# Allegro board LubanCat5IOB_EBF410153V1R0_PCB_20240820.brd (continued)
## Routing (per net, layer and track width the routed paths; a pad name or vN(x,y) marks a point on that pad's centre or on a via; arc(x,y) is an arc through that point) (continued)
HDMI1_EARC-: length 14.2
  TOP w0.114: v1(97.28,77.97) 97.62,78.31 arc(97.67,78.38) 97.68,78.45 97.68,78.64 arc(97.67,78.72) 97.62,78.8 D34.2 97.53,79.1 arc(97.55,79.2) 97.61,79.28 97.63,79.31 arc(97.68,79.38) 97.69,79.46 97.69,80.02 arc(97.83,80.35) 98.16,80.49 98.84,80.49 arc(99.07,80.72) 98.84,80.95 97.27,80.95 arc(96.93,81.09) 96.79,81.43 96.79,81.62 arc(96.73,81.76) 96.59,81.81 96.34,81.81 arc(96.02,81.95) 95.89,82.27 95.89,82.28 arc(96.02,82.62) 96.35,82.75 96.56,82.75 arc(96.72,82.82) 96.79,82.98 96.79,83.1 arc(96.86,83.47) 97.07,83.79 97.42,84.13 arc(97.63,84.45) 97.7,84.82 97.7,84.98 arc(97.63,85.14) 97.47,85.21 97.27,85.21 arc(97.22,85.21) 97.18,85.21 arc(97.09,85.22) 96.99,85.21 arc(96.99,85.21) 96.99,85.21 arc(96.75,85.12) 96.58,84.94 arc(96.57,84.92) 96.56,84.91 arc(96.55,84.88) 96.55,84.84 96.55,84.84 arc(96.54,84.82) 96.53,84.8 arc(96.37,84.43) 96.13,84.11 J17.19
HDMI1_TX_ON: length 50.1
  TOP w0.152: J4.91 v2(86.04,64.36)
  BOTTOM w0.152: R190.1 124.59,75.31 124.18,74.9 120.75,74.9 120.47,75.18 119.08,75.18 118.82,74.93 118.82,74.04 118.57,73.79 117.47,73.79 117.09,73.4 117.09,71.75 116.71,71.37 115.95,71.37 115.57,70.99 115.57,70.36 115.19,69.98 113.83,69.98 112.32,68.47 112.32,64.57 111.06,63.31 88.32,63.31 87.68,63.95 86.45,63.95 v2(86.04,64.36)
HDMI_RX0N_PORT: length 16.8
  TOP w0.114: J18.9 106.89,89.85 108.52,89.85 108.83,90.17 109.45,90.17 109.85,89.77 109.85,89.77 112.38,87.24 112.38,86.87 112.19,86.68 112.19,86.22 112.38,86.03 112.38,85.57 112.19,85.38 112.19,84.93 112.38,84.74 112.38,84.28 112.19,84.09 112.19,83.63 112.38,83.44 112.38,80.83 112.26,80.71 U24.7 U24.4 112.26,79.06 112.39,78.93 112.39,78.34 R206.2
HDMI_RX0P_PORT: length 16.9
  TOP w0.114: J18.7 106.89,91 108.26,91 108.85,90.41 109.55,90.41 109.95,90.01 109.95,90.01 112.62,87.34 112.62,80.84 112.76,80.71 U24.6 U24.5 112.76,79.06 112.63,78.93 112.63,78.37 R205.2
HDMI_RX1N_PORT: length 20.6
  TOP w0.114: R204.2 114.95,76.34 114.95,78.93 114.82,79.06 U23.1 U23.10 114.82,80.72 114.95,80.84 114.95,82.63 114.78,82.8 114.78,83.25 114.95,83.42 114.95,83.66 114.78,83.82 114.78,84.33 114.95,84.5 114.95,84.95 114.78,85.12 114.78,85.63 114.95,85.79 114.95,86.11 109.01,92.04 108.34,92.04 J18.6
HDMI_RX1P_PORT: length 20.5
  TOP w0.114: R203.2 115.19,76.31 115.19,78.93 115.32,79.06 U23.2 U23.9 115.32,80.71 115.19,80.84 115.19,86.21 109.11,92.28 108.34,92.28 J18.4
HDMI_RX2N_PORT: length 21.8
  TOP w0.114: J18.3 106.89,93.31 108.22,93.31 108.61,93.7 108.78,93.7 109.61,92.87 109.61,92.62 109.93,92.29 110.18,92.29 110.51,91.97 110.51,91.72 110.83,91.4 111.08,91.4 111.25,91.22 111.25,91.02 111.58,90.7 111.78,90.7 112.1,90.38 112.1,90.17 112.42,89.85 112.63,89.85 116.45,86.02 116.45,80.84 116.32,80.71 U23.7 U23.4 116.32,79.06 116.45,78.93 116.45,78.34 R202.2
HDMI_RX2P_PORT: length 21.7
  TOP w0.114: R201.2 117.08,77.97 116.69,78.36 116.69,78.93 116.82,79.06 U23.5 U23.6 116.82,80.71 116.69,80.84 116.69,86.12 108.88,93.94 108.67,93.94 108.1,94.51 106.93,94.51 J18.1
HDMI_RX_CEC_M1: length 80.2
  TOP w0.152: v1(127.78,84.71) 128.24,84.25 128.86,84.25 R198.2 128.59,83.37 Q25.2 ; J4.74 82.44,67.32 v2(82.04,66.92)
  ART03 w0.152: v1(127.78,84.71) 127.46,84.39 115.6,84.39 111.18,79.97 108.92,79.97 107.77,78.83 107.19,78.83 106.76,78.4 106.76,77.56 106.25,77.05 96.01,77.05 95.4,76.44 85.85,76.44 85.04,77.26 80.34,77.26 79.96,77.64 79.96,82.62 v1(80.47,83.13)
  BOTTOM w0.152: v1(80.47,83.13) 80.47,81.09 81.41,80.15 81.41,68.34 81.67,68.08 81.67,67.29 v2(82.04,66.92)
HDMI_RX_CEC_PORT: length 34.2
  TOP w0.152: R209.2 129.54,78.6 v1(129.54,79.18) Q25.3
  BOTTOM w0.152: J18.13 105.54,86.19 105.54,82.39 107.8,80.13 113.68,80.13 D44.2 115.39,78.42 126.56,78.42 127.31,79.18 v1(129.54,79.18)
HDMI_RX_CLKN: length 80.7
  TOP w0.114: R208.1 110.88,74.55 110.88,73.95 110.43,73.5 110.43,70.24 110.2,70.02 108.81,70.02 108.44,69.65 108.44,61.65 103.33,56.54 98.41,56.54 94.04,52.17 90.21,52.17 90.04,52.34 89.59,52.34 89.42,52.17 88.96,52.17 88.8,52.34 88.34,52.34 88.18,52.17 87.72,52.17 87.56,52.34 87.1,52.34 86.93,52.17 86.48,52.17 86.31,52.34 85.85,52.34 85.69,52.17 85.23,52.17 85.07,52.34 84.61,52.34 84.44,52.17 83.99,52.17 83.82,52.34 83.36,52.34 83.2,52.17 82.08,52.17 v1(81.81,52.44) ; J4.65 80.84,63.92 v2(80.44,63.52)
  BOTTOM w0.114: v2(80.44,63.52) 80.29,63.37 80.29,62.03 80.42,61.89 81.87,61.89 82.14,61.62 82.14,61.23 81.87,60.95 80.42,60.95 80.29,60.82 80.29,60.63 80.42,60.5 81.87,60.5 82.14,60.22 82.14,59.83 81.87,59.56 80.42,59.56 80.29,59.42 80.29,59.23 80.42,59.1 81.87,59.1 82.14,58.82 82.14,58.43 81.87,58.16 80.42,58.16 80.29,58.03 80.29,57.84 80.42,57.7 81.87,57.7 82.14,57.43 82.14,57.04 81.87,56.76 80.42,56.76 80.29,56.63 80.29,56.44 80.42,56.3 81.87,56.3 82.14,56.03 82.14,55.64 81.87,55.37 80.42,55.37 80.29,55.23 80.29,55.04 80.42,54.91 81.87,54.91 82.14,54.63 82.14,54.24 81.87,53.97 80.42,53.97 80.29,53.83 80.29,52.47 80.61,52.15 81.53,52.15 v1(81.81,52.44)
HDMI_RX_CLKP: length 80.7
  TOP w0.114: R207.1 111.12,74.55 111.12,73.85 110.67,73.4 110.67,70.14 110.3,69.78 108.91,69.78 108.68,69.55 108.68,61.55 103.43,56.3 98.51,56.3 94.14,51.93 82.13,51.93 v1(81.81,51.62) ; J4.63 v2(80.44,64.36)
  BOTTOM w0.114: v1(81.81,51.62) 81.53,51.91 80.51,51.91 80.05,52.37 80.05,53.93 80.32,54.21 81.77,54.21 81.9,54.34 81.9,54.53 81.77,54.67 80.32,54.67 80.05,54.94 80.05,55.33 80.32,55.61 81.77,55.61 81.9,55.74 81.9,55.93 81.77,56.06 80.32,56.06 80.05,56.34 80.05,56.73 80.32,57 81.77,57 81.9,57.14 81.9,57.33 81.77,57.46 80.32,57.46 80.05,57.74 80.05,58.13 80.32,58.4 81.77,58.4 81.9,58.53 81.9,58.72 81.77,58.86 80.32,58.86 80.05,59.13 80.05,59.52 80.32,59.8 81.77,59.8 81.9,59.93 81.9,60.12 81.77,60.25 80.32,60.25 80.05,60.53 80.05,60.92 80.32,61.19 81.77,61.19 81.9,61.33 81.9,61.52 81.77,61.65 80.32,61.65 80.05,61.93 80.05,63.96 v2(80.44,64.36)
HDMI_RX_D0N: length 78.8
  TOP w0.114: J4.61 80.04,63.92 v2(79.64,63.52) ; R206.1 112.01,76.52 112.4,76.13 112.4,74.95 113.25,74.11 113.25,68.49 113.04,68.29 109.59,68.29 109.27,67.97 109.27,67.48 109.55,67.2 110.75,67.2 110.88,67.07 110.88,66.88 110.75,66.75 109.55,66.75 109.27,66.47 109.27,64.15 109.55,63.87 111.56,63.87 111.7,63.74 111.7,63.55 111.56,63.41 109.55,63.41 109.27,63.14 109.27,62.75 109.55,62.47 110.47,62.47 110.6,62.34 110.6,62.15 110.47,62.02 109.55,62.02 109.27,61.74 109.27,60.9 103.77,55.4 98.53,55.4 93.94,50.81 88.89,50.81 88.72,50.99 88.26,50.99 88.08,50.81 87.62,50.81 87.45,50.99 86.99,50.99 86.81,50.81 86.35,50.81 86.18,50.99 85.72,50.99 85.54,50.81 85.08,50.81 84.91,50.99 84.45,50.99 84.27,50.81 83.81,50.81 83.64,50.99 83.18,50.99 83,50.81 81.06,50.81 v1(80.77,51.1)
  BOTTOM w0.114: v1(80.77,51.1) 80.48,50.81 79.74,50.81 79.49,51.07 79.49,63.37 v2(79.64,63.52)
HDMI_RX_D0P: length 78.8
  TOP w0.114: J4.59 v2(79.64,64.36) ; R205.1 113.03,76.52 112.64,76.13 112.64,75.05 113.49,74.21 113.49,68.39 113.14,68.05 109.69,68.05 109.51,67.87 109.51,67.58 109.65,67.45 110.85,67.45 111.12,67.17 111.12,66.78 110.85,66.51 109.65,66.51 109.51,66.37 109.51,64.25 109.65,64.11 111.66,64.11 111.94,63.84 111.94,63.45 111.66,63.17 109.65,63.17 109.51,63.04 109.51,62.85 109.65,62.72 110.57,62.72 110.85,62.44 110.85,62.05 110.57,61.78 109.65,61.78 109.51,61.64 109.51,60.8 103.87,55.16 98.63,55.16 94.04,50.57 81.06,50.57 v1(80.77,50.29)
  BOTTOM w0.114: v1(80.77,50.29) 80.48,50.57 79.64,50.57 79.25,50.97 79.25,63.96 v2(79.64,64.36)
HDMI_RX_D1N: length 74.4
  TOP w0.114: R204.1 114.55,74.49 114.94,74.1 114.94,67.47 114.78,67.31 112.98,67.31 112.67,67.01 112.67,66.56 112.95,66.29 114.79,66.29 114.92,66.16 114.92,65.97 114.79,65.83 112.95,65.83 112.67,65.56 112.67,62.75 104.32,54.4 98.74,54.4 93.91,49.56 88.31,49.56 88.12,49.75 87.66,49.75 87.47,49.56 87.02,49.56 86.82,49.75 86.37,49.75 86.18,49.56 85.72,49.56 85.53,49.75 85.07,49.75 84.88,49.56 84.42,49.56 84.23,49.75 83.78,49.75 83.59,49.56 83.13,49.56 82.94,49.75 82.48,49.75 82.29,49.56 80.16,49.56 v1(79.88,49.83) ; J4.57 79.24,63.92 v2(78.84,63.52)
  BOTTOM w0.114: v1(79.88,49.83) 79.6,49.54 79.07,49.54 78.68,49.94 78.68,63.35 v2(78.84,63.52)
HDMI_RX_D1P: length 74.3
  TOP w0.114: v1(79.88,49.02) 80.18,49.32 94.01,49.32 98.84,54.16 104.42,54.16 112.92,62.65 112.92,65.46 113.05,65.59 114.89,65.59 115.16,65.87 115.16,66.26 114.89,66.53 113.05,66.53 112.92,66.66 112.92,66.91 113.08,67.07 114.88,67.07 115.18,67.37 115.18,74.1 115.57,74.49 R203.1 ; J4.55 v2(78.84,64.36)
  BOTTOM w0.114: v2(78.84,64.36) 78.44,63.95 78.44,49.84 78.97,49.3 79.6,49.3 v1(79.88,49.02)
HDMI_RX_D2N: length 75.3
  TOP w0.114: J4.53 78.44,63.92 v2(78.04,63.52) ; v1(78.87,48.64) 79.15,48.35 81.35,48.35 81.53,48.53 81.98,48.53 82.16,48.35 82.62,48.35 82.8,48.53 83.25,48.53 83.43,48.35 83.89,48.35 84.07,48.53 84.52,48.53 84.7,48.35 85.16,48.35 85.34,48.53 85.79,48.53 85.97,48.35 86.28,48.35 86.43,48.5 86.89,48.5 87.04,48.35 93.95,48.35 98.86,53.25 104.64,53.25 115.89,64.5 115.89,73.65 116.47,74.23 116.47,76.13 116.08,76.52 R202.1
  BOTTOM w0.114: v1(78.87,48.64) 78.58,48.35 78.26,48.35 77.89,48.71 77.89,63.37 v2(78.04,63.52)
HDMI_RX_D2P: length 75.3
  TOP w0.114: R201.1 117.09,76.52 116.71,76.13 116.71,74.13 116.13,73.55 116.13,64.4 104.74,53.01 98.96,53.01 94.05,48.11 79.15,48.11 v1(78.87,47.82) ; J4.51 v2(78.04,64.36)
  BOTTOM w0.114: v1(78.87,47.82) 78.58,48.11 78.16,48.11 77.65,48.61 77.65,63.97 v2(78.04,64.36)
HDMI_RX_DET: length 97.6
  TOP w0.152: v1(80.64,42.46) 81.07,42.03 81.07,31.16 81.61,30.62 81.61,23.66 81.24,23.29 J2.67 ; v1(112.09,43.19) 112.09,50.13 112.6,50.64 116.08,50.64 116.92,51.48 116.92,60.96 117.51,61.55 117.51,68.23 119.51,70.23 119.51,72.96 118.9,73.57 118.9,74.39 117.86,75.44 117.86,77.33 R210.2 118.49,79.96 118.76,80.22 Q29.3
  ART03 w0.152: v1(80.64,42.46) 81.1,42 108.2,42 109.4,43.19 v1(112.09,43.19)
HDMI_RX_HPD_PORT: length 32.3
  BOTTOM w0.152: R214.2 131.74,78.99 131.57,79.17 131.57,80.64 131.32,80.9 124.97,80.9 124.71,80.64 124.71,80.01 124.3,79.59 117.13,79.59 116.46,80.26 116.46,81.53 115.7,82.29 114.94,82.29 D41.2 113.87,81.22 108.43,81.22 106.89,82.77 J18.19
HDMI_RX_HPDOUT_M1: length 80.1
  TOP w0.152: J4.76 v2(82.84,67.76)
  ART03 w0.152: v1(128.78,84.71) 128.15,85.33 117.4,85.33 116.71,86.02 113.28,86.02 112.78,85.51 112.78,82.82 110.64,80.69 106.98,80.69 104.83,78.53 86.23,78.53 85.52,79.24 82.04,79.24 81.64,79.64 81.64,83.96 v1(80.47,85.13)
  BOTTOM w0.152: v2(82.84,67.76) 83.06,67.97 83.06,75.96 82.26,76.76 82.26,80.67 81.38,81.55 81.38,84.83 81.08,85.13 v1(80.47,85.13) ; R212.1 v1(128.78,84.71)
HDMI_RX_SCL_M1: length 76.5
  TOP w0.152: Q24.2 125.29,83.37 R196.2 125.87,83.96 125,84.83 v1(124.18,84.83) ; J4.70 81.64,67.32 v2(81.24,66.92)
  ART03 w0.152: v1(80.47,84.13) 80.98,83.62 80.98,78.37 81.25,78.1 85.11,78.1 85.67,77.54 105.38,77.54 105.69,77.84 105.69,78.17 107.85,80.33 110.97,80.33 115.47,84.83 v1(124.18,84.83)
  BOTTOM w0.152: v2(81.24,66.92) 80.87,67.29 80.87,76.19 81.05,76.37 81.05,80 80.01,81.05 80.01,83.67 v1(80.47,84.13)
HDMI_RX_SDA_M1: length 79.8
  TOP w0.152: v1(122.56,85.87) R199.2 121.98,83.37 Q26.2 ; J4.72 v2(82.04,67.76)
  ART03 w0.152: v1(122.56,85.87) 121.9,86.53 112.5,86.53 112.22,86.25 112.22,82.95 110.46,81.19 106.73,81.19 104.52,78.98 86.61,78.98 85.72,79.87 84.28,79.87 83.97,80.18 83.97,86.04 83.64,86.37 79.88,86.37 79.47,85.96 v1(79.47,85.13)
  BOTTOM w0.152: v1(79.47,85.13) 79.92,84.67 80.7,84.67 81,84.37 81,81.29 81.91,80.39 81.91,76.48 82.55,75.83 82.55,68.27 v2(82.04,67.76)
HDMI_RXCLKN_PORT: length 15.3
  TOP w0.114: R208.2 110.89,76.34 110.89,78.93 110.76,79.06 U24.1 U24.10 110.76,80.71 110.89,80.84 110.89,83.43 109.22,85.1 109.22,85.9 109.02,86.1 109.02,86.56 109.22,86.76 109.22,87.22 109.02,87.42 109.02,87.88 109.22,88.08 109.22,88.32 108.97,88.57 108.34,88.57 J18.12
HDMI_RXCLKP_PORT: length 15.4
  TOP w0.114: J18.10 108.34,88.81 109.07,88.81 109.46,88.42 109.46,85.2 111.13,83.53 111.13,80.84 111.26,80.71 U24.9 U24.2 111.26,79.06 111.13,78.93 111.13,76.31 R207.2
HDMI_RXDDC_SCL_PORT: length 31.9
  TOP w0.152: v1(125.22,80.34) 125.34,80.22 Q24.3 127.85,80.22 128.14,79.93 128.14,77.6 R197.2
  BOTTOM w0.152: J18.15 106.17,85.66 106.17,82.54 108.07,80.64 D43.2 114.85,80.11 115.73,80.11 116.71,79.12 124.84,79.12 125.22,79.5 v1(125.22,80.34)
HDMI_RXDDC_SDA_PORT: length 34.5
  TOP w0.152: v1(124.21,80.34) 124.09,80.22 Q26.3 122.94,79.32 123.16,79.09 127.2,79.09 127.5,78.8 R200.2
  BOTTOM w0.152: v1(124.21,80.34) 123.73,80.81 118.52,80.81 118.06,81.28 118.06,86.21 117.86,86.41 114.51,86.41 114.31,86.21 D42.2 112.9,85.6 112.55,85.95 112.55,87.89 112.17,88.26 109.6,88.26 109.22,87.88 109.22,86.1 108.92,85.8 J18.16
HDMI_TX0_CEC_M0: length 54.5
  TOP w0.152: v1(82.03,70.9) R170.2 82.49,72.1 Q14.2 ; v2(54.72,67.4) 54.33,67.4 54.07,67.66 J3.60
  ART04 w0.152: v1(62.99,82.13) 63.18,82.31 80.59,82.31 80.95,81.95 80.95,79.03 82.03,77.94 v1(82.03,70.9)
  BOTTOM w0.152: v1(62.99,82.13) 62.42,81.55 61.21,81.55 60.93,81.27 60.93,76.47 60.22,75.76 60.22,74.92 59.92,74.61 58.88,74.61 58.57,74.31 58.57,71.87 58.06,71.36 58.06,68.62 57.56,68.11 54.94,68.11 54.72,67.9 v2(54.72,67.4)
HDMI_TX0_CEC_PORT: length 15.1
  TOP w0.152: v1(82.69,78.72) 82.01,78.72 81.53,78.25 Q14.3
  BOTTOM w0.152: J16.13 83.69,85.94 D31.2 82.71,78.74 v1(82.69,78.72)
HDMI_TX0_D0N: length 45.5
  TOP w0.114: J4.37 75.24,64.5 75.16,64.42 75.16,61.66 arc(75.41,61.07) 76,60.82 76.53,60.82 76.71,61 77.16,61 77.34,60.82 77.8,60.82 77.98,61 78.43,61 78.61,60.82 79.07,60.82 79.25,61 79.7,61 79.88,60.82 80.34,60.82 80.52,61 80.97,61 81.15,60.82 81.61,60.82 81.79,61 82.24,61 82.42,60.82 87.92,60.82 arc(88.84,61) 89.62,61.52 90.61,62.52 arc(91.12,63.28) 91.3,64.19 91.3,70.32 arc(91.48,70.74) 91.9,70.92 93.17,70.92 arc(93.33,70.99) 93.4,71.15 93.4,71.41 arc(93.33,71.58) 93.17,71.64 91.78,71.64 arc(91.31,72.11) 91.78,72.58 93.17,72.58 arc(93.33,72.65) 93.4,72.81 93.4,73.05 arc(93.33,73.21) 93.17,73.28 91.54,73.28 arc(91.11,73.46) 90.94,73.88 90.94,74.12 arc(91.08,74.45) 91.41,74.59 92.32,74.59 arc(92.54,74.82) 92.32,75.05 91.41,75.05 arc(91.08,75.18) 90.94,75.52 90.94,76.42 arc(90.91,76.57) 90.82,76.7 C136.1
HDMI_TX0_D0N_PORT: length 17.9
  TOP w0.114: v1(90.55,77.97) 90.87,78.29 arc(90.94,78.4) 90.97,78.53 90.97,78.56 arc(90.95,78.68) 90.88,78.78 D50.2 90.87,78.97 arc(90.92,79.06) 90.94,79.16 90.94,88.28 arc(90.83,88.87) 90.49,89.37 89.93,89.93 arc(89.51,90.21) 89.01,90.31 88.63,90.31 arc(88.51,90.26) 88.46,90.15 arc(88.41,90.03) 88.3,89.98 88.05,89.98 arc(87.94,90.03) 87.89,90.15 arc(87.84,90.26) 87.73,90.31 87.49,90.31 arc(87.27,90.27) 87.08,90.14 86.95,90.01 arc(86.77,89.89) 86.55,89.85 85.71,89.85 85.71,89.84 J16.9
HDMI_TX0_D0P: length 45.5
  TOP w0.114: C135.1 91.3,76.7 arc(91.21,76.57) 91.18,76.42 91.18,75.52 arc(91.25,75.36) 91.41,75.29 92.32,75.29 arc(92.79,74.82) 92.32,74.35 91.41,74.35 arc(91.25,74.28) 91.18,74.12 91.18,73.88 arc(91.28,73.63) 91.54,73.52 93.17,73.52 arc(93.5,73.38) 93.64,73.05 93.64,72.81 arc(93.5,72.48) 93.17,72.34 91.78,72.34 arc(91.55,72.11) 91.78,71.88 93.17,71.88 arc(93.5,71.75) 93.64,71.41 93.64,71.15 arc(93.5,70.82) 93.17,70.68 91.9,70.68 arc(91.65,70.57) 91.54,70.32 91.54,64.19 arc(91.34,63.19) 90.78,62.35 89.79,61.35 arc(88.93,60.78) 87.92,60.58 76,60.58 arc(75.23,60.9) 74.92,61.66 74.92,64.42 74.84,64.5 J4.35
HDMI_TX0_D0P_PORT: length 17.8
  TOP w0.114: J16.7 85.71,91 85.71,91 86.56,91 arc(86.78,90.96) 86.97,90.83 87.08,90.72 arc(87.27,90.59) 87.49,90.55 89.01,90.55 arc(89.6,90.43) 90.1,90.1 90.66,89.54 arc(91.05,88.96) 91.19,88.28 91.19,79.18 arc(91.21,79.07) 91.27,78.98 D51.2 91.28,78.8 arc(91.23,78.72) 91.21,78.63 91.21,78.51 arc(91.25,78.34) 91.35,78.19 v1(91.57,77.97)
HDMI_TX0_D1N: length 41
  TOP w0.114: J4.33 74.44,64.5 74.36,64.42 74.36,61.29 arc(74.48,60.7) 74.81,60.2 arc(75.31,59.87) 75.89,59.76 76.38,59.76 76.53,59.91 76.99,59.91 77.14,59.76 77.6,59.76 77.75,59.91 78.21,59.91 78.36,59.76 78.82,59.76 78.97,59.91 79.43,59.91 79.58,59.76 80.04,59.76 80.19,59.91 80.65,59.91 80.8,59.76 81.26,59.76 81.41,59.91 81.86,59.91 82.02,59.76 82.47,59.76 82.63,59.91 83.08,59.91 83.24,59.76 87.65,59.76 arc(89.05,60.04) 90.24,60.83 91.47,62.06 arc(92.08,62.97) 92.29,64.03 92.29,69.49 arc(92.47,69.93) 92.91,70.11 93.81,70.11 arc(94.19,70.26) 94.35,70.64 94.35,74.89 arc(94.25,75.12) 94.02,75.22 93.67,75.22 arc(93.34,75.36) 93.2,75.69 93.2,76.42 arc(93.17,76.57) 93.08,76.7 C134.1
HDMI_TX0_D1N_PORT: length 21.5
  TOP w0.114: J16.6 86.59,91.89 arc(86.76,92) 86.96,92.04 87.3,92.04 arc(87.36,92.01) 87.39,91.95 arc(87.42,91.89) 87.48,91.86 87.76,91.86 arc(87.82,91.89) 87.85,91.95 arc(87.87,92.01) 87.94,92.04 88.22,92.04 arc(88.28,92.01) 88.31,91.95 arc(88.33,91.89) 88.39,91.86 88.67,91.86 arc(88.74,91.89) 88.76,91.95 arc(88.79,92.01) 88.85,92.04 89.13,92.04 arc(89.25,92.02) 89.36,91.94 91.21,90.09 arc(91.66,89.42) 91.82,88.62 91.82,86.91 arc(91.98,86.54) 92.35,86.38 92.97,86.38 arc(93.26,86.1) 92.97,85.81 92.35,85.81 arc(91.98,85.66) 91.82,85.29 91.82,81.25 arc(91.86,81.03) 91.99,80.85 93.14,79.69 arc(93.18,79.63) 93.2,79.56 93.2,79.47 arc(93.18,79.38) 93.13,79.3 93.11,79.28 arc(93.05,79.2) 93.04,79.1 D52.2 93.12,78.8 arc(93.17,78.72) 93.19,78.63 93.19,78.53 arc(93.16,78.36) 93.07,78.23 v1(92.81,77.97)
HDMI_TX0_D1P: length 41
  TOP w0.114: J4.31 74.04,64.5 74.12,64.42 74.12,61.29 arc(74.25,60.61) 74.64,60.03 arc(75.21,59.65) 75.89,59.51 87.65,59.51 arc(89.14,59.81) 90.41,60.66 91.64,61.89 arc(92.3,62.87) 92.53,64.03 92.53,69.49 arc(92.64,69.76) 92.91,69.86 93.81,69.86 arc(94.36,70.09) 94.59,70.64 94.59,74.89 arc(94.42,75.29) 94.02,75.46 93.67,75.46 arc(93.51,75.53) 93.44,75.69 93.44,76.42 arc(93.47,76.57) 93.56,76.7 C133.1
HDMI_TX0_D1P_PORT: length 21.5
  TOP w0.114: J16.4 86.62,92.4 arc(86.76,92.31) 86.91,92.28 89.13,92.28 arc(89.35,92.24) 89.53,92.11 91.38,90.26 arc(91.89,89.51) 92.06,88.62 92.06,86.91 arc(92.15,86.71) 92.35,86.63 92.97,86.63 arc(93.5,86.1) 92.97,85.57 92.35,85.57 arc(92.15,85.49) 92.06,85.29 92.06,81.25 arc(92.09,81.13) 92.16,81.02 93.32,79.86 arc(93.41,79.72) 93.44,79.56 93.44,79.47 arc(93.46,79.38) 93.51,79.3 93.53,79.28 arc(93.58,79.2) 93.6,79.1 D53.2 93.51,78.79 arc(93.45,78.7) 93.43,78.6 93.43,78.53 arc(93.46,78.38) 93.55,78.25 v1(93.83,77.97)
HDMI_TX0_D2N: length 42.6
  TOP w0.114: J4.29 73.64,64.5 73.56,64.42 73.56,60.65 arc(73.7,59.93) 74.11,59.32 arc(74.64,58.97) 75.26,58.84 75.88,58.84 76.05,59.02 76.51,59.02 76.69,58.84 77.15,58.84 77.32,59.02 77.78,59.02 77.96,58.84 78.42,58.84 78.59,59.02 79.05,59.02 79.23,58.84 79.69,58.84 79.86,59.02 80.32,59.02 80.5,58.84 80.96,58.84 81.13,59.02 81.59,59.02 81.77,58.84 88.18,58.84 arc(89.53,59.11) 90.67,59.87 92.51,61.71 arc(93.24,62.81) 93.5,64.1 93.5,67.73 arc(93.61,68.29) 93.93,68.78 95.07,69.91 arc(95.34,70.32) 95.43,70.79 95.43,76.44 arc(95.41,76.57) 95.34,76.68 C132.1
HDMI_TX0_D2N_PORT: length 22.8
  TOP w0.114: v1(95.05,77.97) 95.31,78.24 arc(95.4,78.37) 95.43,78.53 95.43,78.61 arc(95.42,78.71) 95.36,78.79 D54.2 95.37,78.98 arc(95.43,79.07) 95.45,79.17 95.45,79.44 95.3,79.58 95.3,80.04 95.45,80.19 95.45,80.43 arc(95.42,80.57) 95.34,80.7 95.31,80.72 arc(94.94,81.28) 94.81,81.94 94.81,86.2 arc(94.41,88.17) 93.3,89.84 92.45,90.69 92.16,90.69 91.84,91.01 91.84,91.3 91.51,91.63 91.22,91.63 90.89,91.95 90.89,92.24 90.72,92.41 arc(89.98,92.91) 89.09,93.09 88.5,93.09 arc(88.28,93.13) 88.1,93.26 87.73,93.63 arc(87.62,93.7) 87.49,93.72 87.36,93.72 arc(87.14,93.68) 86.95,93.56 86.89,93.49 arc(86.7,93.36) 86.48,93.32 85.72,93.32 85.71,93.31 J16.3
HDMI_TX0_D2P: length 42.6
  TOP w0.114: J4.27 73.24,64.5 73.32,64.42 73.32,60.65 arc(73.48,59.84) 73.94,59.15 arc(74.55,58.74) 75.26,58.6 88.18,58.6 arc(89.62,58.89) 90.84,59.7 92.68,61.54 arc(93.46,62.72) 93.74,64.1 93.74,67.73 arc(93.83,68.2) 94.1,68.6 95.24,69.74 arc(95.56,70.22) 95.68,70.79 95.68,76.44 arc(95.7,76.57) 95.77,76.68 C131.1
HDMI_TX0_D2P_PORT: length 22.7
  TOP w0.114: v1(96.06,77.97) 95.79,78.24 arc(95.71,78.37) 95.68,78.51 95.68,78.57 arc(95.7,78.68) 95.76,78.78 D65.2 95.77,78.98 arc(95.71,79.07) 95.69,79.17 95.69,80.43 arc(95.64,80.67) 95.51,80.87 95.48,80.89 arc(95.16,81.37) 95.05,81.94 95.05,86.2 arc(94.64,88.26) 93.47,90.01 90.89,92.58 arc(90.07,93.14) 89.09,93.33 88.5,93.33 arc(88.38,93.36) 88.27,93.43 87.9,93.8 arc(87.71,93.92) 87.49,93.97 87.36,93.97 arc(87.14,94.01) 86.95,94.13 86.79,94.3 arc(86.6,94.43) 86.38,94.47 85.72,94.47 85.71,94.46 J16.1
HDMI_TX0_D3N: length 48.1
  TOP w0.114: J4.41 76.04,64.5 75.96,64.42 75.96,62.34 arc(76.13,61.94) 76.53,61.78 77.04,61.78 77.2,61.94 77.66,61.94 77.82,61.78 78.28,61.78 78.45,61.94 78.9,61.94 79.07,61.78 79.53,61.78 79.69,61.94 80.15,61.94 80.31,61.78 80.77,61.78 80.94,61.94 81.39,61.94 81.56,61.78 82.02,61.78 82.18,61.94 82.64,61.94 82.8,61.78 83.26,61.78 83.43,61.94 83.88,61.94 84.05,61.78 87.72,61.78 arc(88.44,61.92) 89.04,62.32 89.96,63.24 arc(90.09,63.43) 90.13,63.65 90.13,64.04 arc(90.06,64.2) 89.9,64.26 89.45,64.26 arc(88.98,64.73) 89.45,65.2 89.9,65.2 arc(90.06,65.27) 90.13,65.43 90.13,65.67 arc(90.06,65.84) 89.9,65.9 89.45,65.9 arc(88.98,66.37) 89.45,66.84 90.16,66.84 arc(90.39,67.07) 90.16,67.3 89.45,67.3 arc(88.98,67.77) 89.45,68.24 90.16,68.24 arc(90.39,68.47) 90.16,68.7 89.45,68.7 arc(88.98,69.17) 89.45,69.64 90.16,69.64 arc(90.39,69.86) 90.16,70.09 89.45,70.09 arc(88.98,70.56) 89.45,71.03 90.16,71.03 arc(90.39,71.26) 90.16,71.49 89.45,71.49 arc(88.98,71.96) 89.45,72.43 90.16,72.43 arc(90.39,72.66) 90.16,72.89 89.45,72.89 arc(88.98,73.36) 89.45,73.83 89.9,73.83 arc(90.06,73.89) 90.13,74.06 90.13,74.3 arc(90.06,74.46) 89.9,74.53 89.12,74.53 arc(88.79,74.66) 88.65,75 88.65,76.39 arc(88.62,76.57) 88.52,76.72 C138.1
HDMI_TX0_D3N_PORT: length 15.1
  TOP w0.114: v1(88.27,77.97) 88.53,78.23 arc(88.62,78.36) 88.65,78.51 88.65,78.58 arc(88.62,78.69) 88.56,78.78 D5.2 88.46,79.09 arc(88.48,79.2) 88.54,79.29 88.56,79.3 arc(88.62,79.39) 88.64,79.5 88.64,80.63 arc(88.75,81.21) 89.08,81.7 89.56,82.18 arc(89.85,82.61) 89.95,83.11 89.95,87.86 arc(89.9,88.09) 89.77,88.29 89.67,88.39 arc(89.47,88.53) 89.23,88.57 88.04,88.57 arc(87.94,88.53) 87.89,88.43 arc(87.85,88.32) 87.75,88.28 87.47,88.28 arc(87.36,88.32) 87.32,88.43 arc(87.28,88.53) 87.18,88.57 86.93,88.57 arc(86.76,88.54) 86.61,88.44 J16.12
HDMI_TX0_D3P: length 48
  TOP w0.114: C137.1 89.03,76.72 arc(88.93,76.57) 88.89,76.39 88.89,75 arc(88.96,74.83) 89.12,74.77 89.9,74.77 arc(90.24,74.63) 90.37,74.3 90.37,74.06 arc(90.24,73.72) 89.9,73.59 89.45,73.59 arc(89.22,73.36) 89.45,73.13 90.16,73.13 arc(90.63,72.66) 90.16,72.19 89.45,72.19 arc(89.22,71.96) 89.45,71.73 90.16,71.73 arc(90.63,71.26) 90.16,70.79 89.45,70.79 arc(89.22,70.56) 89.45,70.33 90.16,70.33 arc(90.63,69.86) 90.16,69.4 89.45,69.4 arc(89.22,69.17) 89.45,68.94 90.16,68.94 arc(90.63,68.47) 90.16,68 89.45,68 arc(89.22,67.77) 89.45,67.54 90.16,67.54 arc(90.63,67.07) 90.16,66.6 89.45,66.6 arc(89.22,66.37) 89.45,66.14 89.9,66.14 arc(90.24,66.01) 90.37,65.67 90.37,65.43 arc(90.24,65.1) 89.9,64.96 89.45,64.96 arc(89.22,64.73) 89.45,64.51 89.9,64.51 arc(90.24,64.37) 90.37,64.04 90.37,63.65 arc(90.31,63.34) 90.13,63.07 89.21,62.15 arc(88.53,61.69) 87.72,61.53 76.53,61.53 arc(75.96,61.77) 75.72,62.34 75.72,64.42 75.64,64.5 J4.39
HDMI_TX0_D3P_PORT: length 15.2
  TOP w0.114: J16.10 86.58,88.98 arc(86.76,88.86) 86.98,88.81 89.23,88.81 arc(89.56,88.75) 89.84,88.56 89.94,88.46 arc(90.12,88.19) 90.19,87.86 90.19,83.11 arc(90.07,82.51) 89.73,82.01 89.25,81.53 arc(88.98,81.12) 88.88,80.63 88.88,79.5 arc(88.9,79.39) 88.96,79.3 88.98,79.29 arc(89.04,79.2) 89.06,79.09 D14.2 88.96,78.79 arc(88.91,78.7) 88.89,78.6 88.89,78.53 arc(88.92,78.38) 89,78.25 v1(89.28,77.97)
HDMI_TX0_HPD_M0: length 10
  TOP w0.152: J4.92 86.04,67.32 v2(86.44,66.92)
  BOTTOM w0.152: v2(86.44,66.92) 86.92,66.44 88.01,66.44 88.39,66.82 R157.2 91.95,66.83 91.95,67.58 91.4,68.13 Q8.3
HDMI_TX0_SBDN: length 39.7
  TOP w0.114: C140.1 86.14,76.68 arc(86.21,76.57) 86.24,76.44 86.24,75.86 arc(86.38,75.53) 86.71,75.39 87.39,75.39 arc(87.7,75.08) 87.39,74.77 86.27,74.77 arc(85.92,74.62) 85.78,74.28 85.78,74.18 arc(85.92,73.85) 86.25,73.71 87.72,73.71 arc(87.93,73.63) 88.01,73.43 88.01,72.76 arc(87.94,72.6) 87.78,72.53 86.78,72.53 arc(86.31,72.06) 86.78,71.59 87.86,71.59 arc(88.02,71.53) 88.09,71.36 88.09,70.6 arc(88.02,70.43) 87.86,70.37 86.27,70.37 arc(85.8,69.9) 86.27,69.43 87.86,69.43 arc(88.02,69.36) 88.09,69.2 88.09,63.2 arc(88.05,63.01) 87.94,62.84 arc(87.77,62.73) 87.57,62.69 84.9,62.69 84.73,62.85 84.28,62.85 84.11,62.69 83.66,62.69 83.49,62.85 83.03,62.85 82.87,62.69 82.41,62.69 82.25,62.85 81.79,62.85 81.62,62.69 81.17,62.69 81,62.85 80.54,62.85 80.38,62.69 79.92,62.69 79.76,62.85 79.3,62.85 79.13,62.69 78.68,62.69 78.51,62.85 78.05,62.85 77.89,62.69 77.58,62.69 arc(77.28,62.81) 77.16,63.11 77.16,64.42 77.24,64.5 J4.47
HDMI_TX0_SBDP: length 39.6
  TOP w0.114: J4.45 76.84,64.5 76.92,64.42 76.92,63.11 arc(77.11,62.64) 77.58,62.45 87.57,62.45 arc(87.86,62.51) 88.11,62.67 arc(88.27,62.91) 88.33,63.2 88.33,69.2 arc(88.19,69.53) 87.86,69.67 86.27,69.67 arc(86.04,69.9) 86.27,70.13 87.86,70.13 arc(88.19,70.26) 88.33,70.6 88.33,71.36 arc(88.19,71.7) 87.86,71.83 86.78,71.83 arc(86.55,72.06) 86.78,72.29 87.78,72.29 arc(88.11,72.43) 88.25,72.76 88.25,73.43 arc(88.1,73.8) 87.72,73.95 86.25,73.95 arc(86.09,74.02) 86.02,74.18 86.02,74.28 arc(86.1,74.45) 86.27,74.53 87.39,74.53 arc(87.94,75.08) 87.39,75.63 86.71,75.63 arc(86.55,75.7) 86.48,75.86 86.48,76.44 arc(86.51,76.57) 86.58,76.68 C139.1
HDMI_TX0_SCL_M0: length 43.7
  TOP w0.152: J3.56 53.27,66.54 53.81,66 64.19,66 v1(65.53,67.35) ; v1(85.08,70.9) R151.2 85.53,72.1 Q6.2
  ART03 w0.152: v1(65.53,67.35) 67.03,67.35 70.61,63.77 75.27,63.77 76.61,65.12 81.38,65.12 81.64,65.37 81.64,69.64 82.25,70.25 84.43,70.25 v1(85.08,70.9)
HDMI_TX0_SCL_PORT: length 14.8
  TOP w0.152: v1(84.84,76.72) 84.58,76.47 R152.2 83.56,75.21 83.78,74.98 Q6.3
  BOTTOM w0.152: J16.15 84.65,85.74 84.65,81.42 85.29,80.78 85.29,79.72 84.84,79.27 D29.2 84.48,78.74 84.33,78.59 84.33,77.23 v1(84.84,76.72)
HDMI_TX0_SDA_M0: length 48.4
  TOP w0.152: v1(64.53,67.35) 63.59,66.4 53.98,66.4 53.67,66.71 J3.58
  ART03 w0.152: v1(64.53,67.35) 65.37,68.19 68.2,68.19 68.5,67.88 68.5,66.49 70.14,64.85 75.49,64.85 76.34,65.7 76.86,65.7 77.53,66.37 80.34,66.37 80.82,66.85 80.82,70.35 81.99,71.52 86.85,71.52 v1(87.36,71.01)
  BOTTOM w0.152: v1(87.36,71.01) 87.55,71.2 Q7.2 90.2,71.65 C142.2 90.94,71.64 R154.2
HDMI_TX0_SDA_PORT: length 16.3
  BOTTOM w0.152: J16.16 86.92,85.16 86.92,84.26 86.49,83.82 86.49,81.91 87.5,80.9 87.5,79.77 87.12,79.39 D28.2 86.76,78.74 86.54,78.53 86.54,75.53 86.36,75.35 R155.2 86.86,72.15 Q7.3
HDMI_TX1_CEC_M0: length 105.2
  TOP w0.152: J1.59 54.07,36.63 54.38,36.93 66.93,36.93 67.23,37.24 67.23,45.25 67.54,45.56 76.02,45.56 76.33,45.86 76.33,51.81 v1(75.82,52.32)
  ART03 w0.152: v1(110.52,52.97) 78.46,52.97 77.32,51.83 76.31,51.83 v1(75.82,52.32)
  ART04 w0.152: v1(111.76,67.31) 111.76,54.22 v1(110.52,52.97)
  BOTTOM w0.152: v1(111.76,67.31) 111.76,67.95 R191.2 111.05,67.75 Q23.2
HDMI_TX1_CEC_PORT: length 34.6
  ART04 w0.152: v1(109.35,68.71) 103.83,68.71 103.5,69.03 v1(103.5,74.01)
  BOTTOM w0.152: v1(109.35,68.71) Q23.3 107.43,68.71 R354.2 ; J17.13 94.87,86.32 94.87,81.29 95.78,80.38 D38.2 96.54,78.75 97.66,78.75 97.92,78.5 97.92,74.9 98.81,74.01 v1(103.5,74.01)
HDMI_TX1_D0N: length 69.4
  TOP w0.114: J4.13 70.44,64.5 70.36,64.42 70.36,57.64 arc(70.5,56.96) 70.88,56.39 71.15,56.12 arc(71.6,55.82) 72.13,55.72 73.15,55.72 73.31,55.87 73.76,55.87 73.92,55.72 74.37,55.72 74.53,55.87 74.98,55.87 75.13,55.72 75.59,55.72 75.74,55.87 76.2,55.87 76.35,55.72 76.81,55.72 76.96,55.87 77.42,55.87 77.57,55.72 78.03,55.72 78.18,55.87 78.64,55.87 78.79,55.72 79.25,55.72 79.4,55.87 79.86,55.87 80.01,55.72 92.01,55.72 arc(92.83,55.88) 93.53,56.35 96.66,59.48 arc(97.44,59.99) 98.35,60.17 100.44,60.17 arc(101.09,60.31) 101.65,60.68 103.69,62.72 arc(104.14,63.4) 104.31,64.21 104.31,66.56 arc(104.24,66.73) 104.08,66.79 103.7,66.79 arc(103.23,67.26) 103.7,67.73 104.08,67.73 arc(104.31,67.96) 104.08,68.19 103.7,68.19 arc(103.23,68.66) 103.7,69.13 104.08,69.13 arc(104.31,69.36) 104.08,69.59 103.7,69.59 arc(103.23,70.06) 103.7,70.53 104.08,70.53 arc(104.31,70.76) 104.08,70.98 103.7,70.98 arc(103.23,71.45) 103.7,71.92 104.08,71.92 arc(104.31,72.15) 104.08,72.38 103.7,72.38 arc(103.23,72.85) 103.7,73.32 104.08,73.32 arc(104.24,73.39) 104.31,73.55 104.31,74.32 arc(104.18,74.61) 103.89,74.73 102.72,74.73 arc(102.33,74.89) 102.17,75.28 102.17,76.47 arc(102.14,76.57) 102.09,76.66 C148.1
HDMI_TX1_D0N_PORT: length 17.8
  TOP w0.114: v1(101.78,77.97) 102.03,78.23 arc(102.13,78.36) 102.16,78.53 102.16,78.63 arc(102.14,78.72) 102.09,78.8 D68.2 102,79.1 arc(102.02,79.2) 102.08,79.28 102.09,79.3 arc(102.15,79.38) 102.17,79.47 102.17,87.84 arc(102.08,88.25) 101.86,88.59 100.56,89.89 arc(100.09,90.2) 99.54,90.31 99,90.31 arc(98.9,90.27) 98.86,90.17 arc(98.82,90.07) 98.72,90.03 98.54,90.03 arc(98.44,90.07) 98.4,90.17 arc(98.36,90.27) 98.27,90.31 98.02,90.31 arc(97.83,90.27) 97.67,90.16 97.53,90.02 arc(97.34,89.9) 97.12,89.85 96.52,89.85 96.51,89.84 J17.9
HDMI_TX1_D0P: length 69.4
  TOP w0.114: J4.11 70.04,64.5 70.12,64.42 70.12,57.64 arc(70.27,56.87) 70.71,56.22 70.98,55.95 arc(71.5,55.6) 72.13,55.48 92.01,55.48 arc(92.93,55.66) 93.7,56.18 96.83,59.3 arc(97.53,59.77) 98.35,59.93 100.44,59.93 arc(101.18,60.08) 101.82,60.5 103.86,62.55 arc(104.37,63.31) 104.55,64.21 104.55,66.56 arc(104.41,66.9) 104.08,67.03 103.7,67.03 arc(103.47,67.26) 103.7,67.49 104.08,67.49 arc(104.55,67.96) 104.08,68.43 103.7,68.43 arc(103.47,68.66) 103.7,68.89 104.08,68.89 arc(104.55,69.36) 104.08,69.83 103.7,69.83 arc(103.47,70.06) 103.7,70.29 104.08,70.29 arc(104.55,70.76) 104.08,71.23 103.7,71.23 arc(103.47,71.45) 103.7,71.68 104.08,71.68 arc(104.55,72.15) 104.08,72.62 103.7,72.62 arc(103.47,72.85) 103.7,73.08 104.08,73.08 arc(104.41,73.22) 104.55,73.55 104.55,74.32 arc(104.36,74.78) 103.89,74.97 102.72,74.97 arc(102.5,75.06) 102.41,75.28 102.41,76.47 arc(102.43,76.57) 102.49,76.66 C147.1
HDMI_TX1_D0P_PORT: length 17.9
  TOP w0.114: J17.7 96.51,91 96.51,91 97.13,91 arc(97.35,90.96) 97.53,90.83 97.65,90.72 arc(97.83,90.59) 98.05,90.55 99.54,90.55 arc(100.18,90.42) 100.73,90.06 102.03,88.76 arc(102.31,88.34) 102.41,87.84 102.41,79.47 arc(102.43,79.38) 102.48,79.3 102.5,79.28 arc(102.55,79.2) 102.57,79.1 D69.2 102.48,78.79 arc(102.42,78.7) 102.4,78.6 102.4,78.53 arc(102.43,78.38) 102.52,78.25 v1(102.79,77.97)
HDMI_TX1_D1N: length 66.7
  TOP w0.114: J4.9 69.64,64.5 69.56,64.42 69.56,56.96 arc(69.74,56.06) 70.25,55.29 arc(70.25,55.29) 70.25,55.29 arc(70.68,55) 71.18,54.9 73.08,54.9 73.23,55.06 73.69,55.06 73.84,54.9 74.3,54.9 74.45,55.06 74.91,55.06 75.06,54.9 75.52,54.9 75.67,55.06 76.13,55.06 76.28,54.9 76.74,54.9 76.89,55.06 77.35,55.06 77.5,54.9 77.96,54.9 78.11,55.06 78.57,55.06 78.72,54.9 79.18,54.9 79.3,55.03 79.81,55.03 79.94,54.9 80.18,54.9 80.31,55.03 80.92,55.03 81.04,54.9 92.08,54.9 arc(93.25,55.14) 94.24,55.8 97.02,58.58 arc(97.82,59.11) 98.76,59.3 100.95,59.3 arc(101.53,59.41) 102.02,59.74 104.52,62.24 arc(104.96,62.91) 105.12,63.69 105.12,65.96 arc(105.26,66.29) 105.59,66.43 105.67,66.43 arc(105.8,66.48) 105.85,66.61 105.85,66.65 arc(105.79,66.82) 105.63,66.88 105.59,66.88 arc(105.12,67.35) 105.59,67.82 105.63,67.82 arc(105.79,67.89) 105.85,68.05 arc(105.79,68.21) 105.63,68.28 105.59,68.28 arc(105.12,68.75) 105.59,69.22 105.63,69.22 arc(105.79,69.28) 105.85,69.44 105.85,69.45 arc(105.79,69.61) 105.63,69.68 105.59,69.68 arc(105.12,70.15) 105.59,70.62 105.67,70.62 arc(105.8,70.67) 105.85,70.8 105.85,70.84 arc(105.79,71.01) 105.63,71.07 105.59,71.07 arc(105.26,71.21) 105.12,71.54 105.12,74.62 arc(105.06,74.92) 104.88,75.18 104.68,75.39 arc(104.45,75.72) 104.37,76.12 104.37,76.5 arc(104.36,76.6) 104.3,76.68 C146.1
HDMI_TX1_D1N_PORT: length 19.9
  TOP w0.114: v1(104.01,77.97) 104.29,78.25 arc(104.38,78.38) 104.41,78.53 104.41,78.6 arc(104.39,78.7) 104.33,78.79 D70.2 104.24,79.09 arc(104.26,79.2) 104.32,79.29 104.33,79.3 arc(104.39,79.39) 104.41,79.5 104.41,80.73 arc(104.46,80.95) 104.58,81.14 104.96,81.52 arc(105.04,81.63) 105.06,81.75 105.06,85.4 104.9,85.56 104.9,86.12 105.06,86.28 105.06,86.52 arc(104.97,86.95) 104.73,87.32 104.55,87.5 104.24,87.5 103.91,87.82 103.91,88.14 100.6,91.44 arc(100.5,91.52) 100.37,91.54 99.13,91.54 arc(98.91,91.58) 98.72,91.71 98.49,91.94 arc(98.38,92.02) 98.25,92.04 97.78,92.04 arc(97.56,92) 97.38,91.87 J17.6
HDMI_TX1_D1P: length 66.7
  TOP w0.114: J4.7 69.24,64.5 69.32,64.42 69.32,56.96 arc(69.52,55.96) 70.08,55.12 arc(70.59,54.78) 71.18,54.66 92.08,54.66 arc(93.34,54.91) 94.41,55.63 97.19,58.41 arc(97.91,58.89) 98.76,59.06 100.95,59.06 arc(101.62,59.19) 102.19,59.57 104.69,62.07 arc(105.19,62.81) 105.36,63.69 105.36,65.96 arc(105.43,66.12) 105.59,66.18 105.67,66.18 arc(105.97,66.31) 106.1,66.61 106.1,66.65 arc(105.96,66.99) 105.63,67.12 105.59,67.12 arc(105.36,67.35) 105.59,67.58 105.63,67.58 arc(105.96,67.72) 106.1,68.05 arc(105.96,68.38) 105.63,68.52 105.59,68.52 arc(105.36,68.75) 105.59,68.98 105.63,68.98 arc(105.96,69.11) 106.1,69.44 106.1,69.45 arc(105.96,69.78) 105.63,69.92 105.59,69.92 arc(105.36,70.15) 105.59,70.37 105.67,70.37 arc(105.97,70.5) 106.1,70.8 106.1,70.84 arc(105.96,71.18) 105.63,71.31 105.59,71.31 arc(105.43,71.38) 105.36,71.54 105.36,74.62 arc(105.28,75.01) 105.05,75.35 104.85,75.56 arc(104.68,75.81) 104.62,76.12 104.62,76.47 arc(104.63,76.55) 104.67,76.61 C145.1
HDMI_TX1_D1P_PORT: length 20
  TOP w0.114: J17.4 97.38,92.45 arc(97.56,92.33) 97.78,92.28 98.25,92.28 arc(98.47,92.24) 98.66,92.11 98.89,91.88 arc(99,91.81) 99.13,91.78 100.37,91.78 arc(100.59,91.74) 100.78,91.61 104.9,87.49 arc(105.2,87.04) 105.3,86.52 105.3,81.75 arc(105.26,81.54) 105.13,81.35 104.75,80.97 arc(104.68,80.86) 104.65,80.73 104.65,79.5 arc(104.68,79.39) 104.73,79.3 104.75,79.29 arc(104.81,79.2) 104.83,79.09 D71.2 104.73,78.78 arc(104.67,78.69) 104.65,78.58 104.65,78.51 arc(104.68,78.36) 104.76,78.23 v1(105.03,77.97)
HDMI_TX1_D2N: length 66.3
  TOP w0.114: J4.5 68.84,64.5 68.76,64.42 68.76,55.97 arc(69.33,54.59) 70.71,54.02 73.17,54.02 73.32,54.17 73.78,54.17 73.93,54.02 74.39,54.02 74.54,54.17 75,54.17 75.15,54.02 75.61,54.02 75.76,54.17 76.22,54.17 76.37,54.02 76.83,54.02 76.98,54.17 77.43,54.17 77.59,54.02 78.04,54.02 78.25,54.22 78.6,54.22 78.81,54.02 92.31,54.02 arc(93.61,54.27) 94.71,55.01 97.19,57.49 arc(98.1,58.1) 99.16,58.31 101.43,58.31 arc(102.1,58.44) 102.68,58.83 105.93,62.08 arc(106.47,62.89) 106.66,63.84 106.66,76.42 arc(106.63,76.57) 106.55,76.7 C144.1
HDMI_TX1_D2N_PORT: length 22.8
  TOP w0.114: J17.3 96.51,93.31 96.52,93.31 97.08,93.31 arc(97.3,93.36) 97.48,93.48 97.63,93.63 arc(97.78,93.73) 97.96,93.76 98.06,93.76 arc(98.16,93.74) 98.25,93.68 98.68,93.26 arc(99.21,92.9) 99.85,92.77 100.37,92.77 arc(100.58,92.73) 100.76,92.61 105.52,87.85 arc(105.9,87.28) 106.04,86.61 106.04,84.22 105.79,83.98 105.79,83.57 106.04,83.33 106.04,82.87 105.82,82.65 105.82,82.19 106.04,81.98 106.04,81.63 arc(106.08,81.41) 106.2,81.23 106.59,80.84 arc(106.66,80.73) 106.69,80.61 106.69,79.47 arc(106.67,79.38) 106.61,79.3 106.6,79.28 arc(106.54,79.2) 106.52,79.1 D72.2 106.61,78.8 arc(106.66,78.72) 106.68,78.63 106.68,78.54 arc(106.65,78.39) 106.56,78.26 v1(106.27,77.97)
HDMI_TX1_D2P: length 66.4
  TOP w0.114: C143.1 107.02,76.7 arc(106.93,76.57) 106.9,76.42 106.9,63.84 arc(106.69,62.8) 106.1,61.91 102.85,58.66 arc(102.2,58.22) 101.43,58.07 99.16,58.07 arc(98.19,57.87) 97.36,57.32 94.88,54.84 arc(93.7,54.05) 92.31,53.77 70.71,53.77 arc(69.16,54.42) 68.52,55.97 68.52,64.42 68.44,64.5 J4.3
HDMI_TX1_D2P_PORT: length 22.8
  TOP w0.114: v1(107.29,77.97) 107.05,78.21 arc(106.95,78.35) 106.92,78.51 106.92,78.6 arc(106.94,78.7) 107,78.79 D73.2 107.09,79.1 arc(107.07,79.2) 107.02,79.28 107,79.3 arc(106.95,79.38) 106.93,79.47 106.93,80.61 arc(106.88,80.83) 106.76,81.01 106.37,81.4 arc(106.3,81.51) 106.28,81.63 106.28,86.61 arc(106.12,87.37) 105.69,88.02 100.93,92.78 arc(100.67,92.95) 100.37,93.01 99.85,93.01 arc(99.31,93.12) 98.85,93.43 98.42,93.85 arc(98.25,93.96) 98.06,94 98.02,94 arc(97.81,94.05) 97.63,94.17 97.49,94.3 arc(97.31,94.43) 97.09,94.47 96.09,94.47 J17.1
HDMI_TX1_D3N: length 71.9
  TOP w0.114: J4.17 71.24,64.5 71.16,64.42 71.16,58.19 arc(71.3,57.5) 71.69,56.91 arc(72.07,56.66) 72.52,56.57 73.21,56.57 73.4,56.76 73.86,56.76 74.05,56.57 74.51,56.57 74.7,56.76 75.15,56.76 75.34,56.57 75.8,56.57 75.99,56.76 76.45,56.76 76.64,56.57 77.1,56.57 77.29,56.76 77.74,56.76 77.94,56.57 78.39,56.57 78.58,56.76 79.04,56.76 79.23,56.57 91.56,56.57 arc(92.3,56.71) 92.92,57.13 96.92,61.13 arc(97.07,61.23) 97.25,61.27 97.5,61.27 arc(97.66,61.33) 97.73,61.5 97.73,61.69 arc(97.86,61.99) 98.16,62.12 98.2,62.12 arc(98.53,61.98) 98.67,61.65 98.67,61.24 arc(98.9,61.01) 99.13,61.24 99.13,61.69 arc(99.25,61.99) 99.55,62.12 99.6,62.12 arc(99.93,61.98) 100.07,61.65 100.07,61.5 arc(100.14,61.33) 100.3,61.27 100.54,61.27 arc(100.91,61.34) 101.23,61.55 102.21,62.53 arc(102.43,62.87) 102.51,63.27 102.51,63.48 arc(102.65,63.8) 102.96,63.93 103.19,63.93 arc(103.42,64.16) 103.19,64.39 102.86,64.39 arc(102.39,64.86) 102.86,65.33 103.21,65.33 arc(103.35,65.39) 103.42,65.54 103.42,65.56 arc(103.35,65.72) 103.19,65.79 102.98,65.79 arc(102.65,65.92) 102.51,66.26 102.51,70.58 arc(102.39,70.87) 102.1,71 100.23,71 arc(99.88,71.14) 99.73,71.49 99.73,71.62 arc(99.87,71.95) 100.2,72.09 102.14,72.09 arc(102.48,72.43) 102.14,72.77 100.35,72.77 arc(99.93,72.94) 99.76,73.36 arc(99.93,73.77) 100.35,73.95 101.26,73.95 arc(101.49,74.18) 101.26,74.4 100.4,74.4 arc(100.07,74.54) 99.93,74.87 99.93,76.45 arc(99.91,76.57) 99.84,76.68 C150.1
HDMI_TX1_D3N_PORT: length 14.8
  TOP w0.114: J17.12 97.38,88.41 arc(97.56,88.53) 97.78,88.57 98.02,88.57 arc(98.12,88.53) 98.15,88.44 arc(98.19,88.34) 98.29,88.31 98.48,88.31 arc(98.57,88.34) 98.61,88.44 arc(98.65,88.53) 98.75,88.57 99.28,88.57 arc(99.88,88.45) 100.4,88.11 100.54,87.97 arc(100.77,87.62) 100.85,87.22 100.85,81.73 arc(100.83,81.61) 100.75,81.5 100.17,80.92 arc(99.99,80.65) 99.93,80.34 99.93,79.47 arc(99.91,79.38) 99.86,79.3 99.84,79.28 arc(99.79,79.2) 99.77,79.1 D66.2 99.87,78.78 arc(99.93,78.69) 99.95,78.58 99.95,78.53 arc(99.92,78.39) 99.84,78.27 v1(99.54,77.97)
HDMI_TX1_D3P: length 71.9
  TOP w0.114: C149.1 100.27,76.68 arc(100.2,76.57) 100.17,76.45 100.17,74.87 arc(100.24,74.71) 100.4,74.65 101.26,74.65 arc(101.73,74.18) 101.26,73.71 100.35,73.71 arc(100.1,73.6) 100,73.36 arc(100.1,73.11) 100.35,73.01 102.14,73.01 arc(102.72,72.43) 102.14,71.85 100.2,71.85 arc(100.04,71.78) 99.97,71.62 99.97,71.49 arc(100.05,71.31) 100.23,71.24 102.1,71.24 arc(102.56,71.04) 102.76,70.58 102.76,66.26 arc(102.82,66.09) 102.98,66.03 103.19,66.03 arc(103.52,65.89) 103.66,65.56 103.66,65.54 arc(103.53,65.22) 103.21,65.09 102.86,65.09 arc(102.63,64.86) 102.86,64.63 103.19,64.63 arc(103.66,64.16) 103.19,63.69 102.96,63.69 arc(102.82,63.63) 102.76,63.48 102.76,63.27 arc(102.66,62.78) 102.38,62.36 101.4,61.38 arc(101,61.12) 100.54,61.03 100.3,61.03 arc(99.96,61.16) 99.83,61.5 99.83,61.65 arc(99.76,61.81) 99.6,61.88 99.55,61.88 arc(99.42,61.82) 99.37,61.69 99.37,61.24 arc(98.9,60.77) 98.43,61.24 98.43,61.65 arc(98.36,61.81) 98.2,61.88 98.16,61.88 arc(98.03,61.82) 97.97,61.69 97.97,61.5 arc(97.84,61.16) 97.5,61.03 97.25,61.03 arc(97.16,61.01) 97.09,60.96 93.09,56.96 arc(92.39,56.49) 91.56,56.33 72.52,56.33 arc(71.98,56.43) 71.52,56.74 arc(71.08,57.4) 70.92,58.19 70.92,64.42 70.84,64.5 J4.15
HDMI_TX1_D3P_PORT: length 14.8
  TOP w0.114: J17.10 97.38,88.98 arc(97.56,88.86) 97.78,88.81 99.28,88.81 arc(99.98,88.68) 100.57,88.28 100.71,88.14 arc(100.99,87.71) 101.09,87.22 101.09,81.73 arc(101.05,81.52) 100.92,81.33 100.34,80.75 arc(100.22,80.56) 100.17,80.34 100.17,79.47 arc(100.19,79.38) 100.24,79.3 100.26,79.28 arc(100.32,79.2) 100.33,79.1 D67.2 100.25,78.8 arc(100.21,78.73) 100.19,78.65 100.19,78.53 arc(100.23,78.35) 100.32,78.2 v1(100.56,77.97)
HDMI_TX1_HPD_M0: length 42.1
  TOP w0.152: J4.94 v2(86.44,67.76)
  BOTTOM w0.152: v2(86.44,67.76) 85.88,67.19 85.88,66.03 85.57,65.72 85.14,65.72 84.84,65.42 84.84,63.26 85.14,62.96 111.88,62.96 112.9,63.98 112.9,67.84 113.27,68.21 R178.2 115.05,68.58 Q17.3
HDMI_TX1_SBDN: length 73.9
  TOP w0.114: C152.1 97.52,76.73 arc(97.63,76.57) 97.67,76.37 97.67,76.09 arc(97.81,75.76) 98.14,75.62 98.84,75.62 arc(99.07,75.4) 98.84,75.17 97.25,75.17 arc(96.78,74.7) 97.25,74.23 98.74,74.23 arc(98.97,74) 98.74,73.77 97.25,73.77 arc(96.78,73.3) 97.25,72.83 98.74,72.83 arc(98.97,72.6) 98.74,72.37 97.28,72.37 arc(96.91,72.22) 96.75,71.85 96.75,70.61 arc(96.92,70.22) 97.31,70.06 97.55,70.06 arc(97.88,70.19) 98.02,70.53 98.02,71.05 arc(98.25,71.27) 98.48,71.05 98.48,70.53 arc(98.61,70.19) 98.95,70.06 101.09,70.06 arc(101.36,69.94) 101.47,69.67 101.47,63.45 arc(101.35,63.14) 101.05,63.02 96.52,63.02 arc(96.23,62.96) 95.98,62.79 94.63,61.45 arc(94.49,61.12) 94.63,60.78 94.8,60.62 arc(94.86,60.46) 94.8,60.3 94.79,60.3 arc(94.63,60.23) 94.47,60.3 94.31,60.46 arc(93.64,60.46) 93.64,59.8 93.81,59.63 arc(93.87,59.47) 93.81,59.32 93.8,59.31 arc(93.64,59.24) 93.48,59.31 93.32,59.47 arc(92.65,59.47) 92.65,58.81 92.82,58.64 arc(92.89,58.48) 92.82,58.33 92.82,58.32 arc(92.65,58.26) 92.49,58.32 92.33,58.48 arc(92,58.62) 91.67,58.48 91.4,58.22 arc(90.5,57.62) 89.44,57.41 79.55,57.41 79.39,57.57 78.93,57.57 78.77,57.41 78.31,57.41 78.14,57.57 77.69,57.57 77.52,57.41 77.06,57.41 76.9,57.57 76.44,57.57 76.28,57.41 75.82,57.41 75.66,57.57 75.2,57.57 75.03,57.41 74.58,57.41 74.41,57.57 73.95,57.57 73.79,57.41 73.11,57.41 arc(72.81,57.47) 72.55,57.64 arc(72.41,57.85) 72.36,58.1 72.36,64.42 72.44,64.5 J4.23
HDMI_TX1_SBDP: length 73.9
  TOP w0.114: J4.21 72.04,64.5 72.12,64.42 72.12,58.1 arc(72.19,57.76) 72.38,57.47 arc(72.72,57.24) 73.11,57.16 89.44,57.16 arc(90.59,57.39) 91.57,58.05 91.84,58.31 arc(92,58.38) 92.16,58.31 92.32,58.15 arc(92.65,58.01) 92.99,58.15 92.99,58.16 arc(93.13,58.48) 92.99,58.81 92.83,58.98 arc(92.83,59.3) 93.15,59.3 93.31,59.14 arc(93.64,59) 93.97,59.14 93.98,59.15 arc(94.11,59.47) 93.98,59.8 93.81,59.97 arc(93.81,60.29) 94.14,60.29 94.3,60.13 arc(94.63,59.99) 94.96,60.13 94.97,60.13 arc(95.1,60.46) 94.97,60.79 94.8,60.95 arc(94.73,61.12) 94.8,61.28 96.15,62.62 arc(96.32,62.74) 96.52,62.78 101.05,62.78 arc(101.52,62.97) 101.71,63.45 101.71,69.67 arc(101.53,70.11) 101.09,70.3 98.95,70.3 arc(98.78,70.36) 98.72,70.53 98.72,71.05 arc(98.25,71.52) 97.78,71.05 97.78,70.53 arc(97.71,70.36) 97.55,70.3 97.31,70.3 arc(97.09,70.39) 97,70.61 97,71.85 arc(97.08,72.05) 97.28,72.13 98.74,72.13 arc(99.21,72.6) 98.74,73.07 97.25,73.07 arc(97.02,73.3) 97.25,73.53 98.74,73.53 arc(99.21,74) 98.74,74.47 97.25,74.47 arc(97.02,74.7) 97.25,74.93 98.84,74.93 arc(99.31,75.4) 98.84,75.87 98.14,75.87 arc(97.98,75.93) 97.91,76.09 97.91,76.37 arc(97.95,76.57) 98.06,76.73 C151.1
HDMI_TX1_SCL_M0: length 109
  TOP w0.152: J1.61 54.47,36.23 54.78,36.53 67.47,36.53 67.78,36.84 67.78,44.82 68.08,45.13 76.78,45.13 77.22,45.56 77.22,51.93 v1(76.82,52.32)
  ART03 w0.152: v1(111.52,52.97) 111.01,53.48 77.98,53.48 v1(76.82,52.32)
  ART04 w0.152: v1(111.68,70.89) 112.22,70.36 112.22,53.68 v1(111.52,52.97)
  BOTTOM w0.152: v1(111.68,70.89) 111.51,71.07 R172.2 110.78,71.64 Q15.2
HDMI_TX1_SCL_PORT: length 23.4
  BOTTOM w0.152: J17.15 95.45,85.74 95.45,82.62 97.56,80.51 D36.2 98.3,78.78 98.3,76.09 99.91,74.47 103.78,74.47 104.47,73.79 105.91,73.79 R173.2
  BOTTOM w0.173: R173.2 107.56,72.13 Q15.3
HDMI_TX1_SDA_M0: length 112.8
  TOP w0.152: v1(69.85,41.42) 68.53,41.42 68.22,41.11 68.22,36.44 67.92,36.13 55.18,36.13 54.87,35.83 J1.63
  BOTTOM w0.152: v1(69.85,41.42) 74.85,41.42 75.36,41.92 81.86,41.92 82.17,42.23 82.17,43.68 83.03,44.54 83.03,62.16 83.39,62.52 113.11,62.52 113.41,62.83 113.41,66.45 113.69,66.72 116.51,66.72 116.92,67.13 116.92,70.83 117.27,71.18 Q16.2 118.52,71.64 C154.2 119.27,71.62 R175.2
HDMI_TX1_SDA_PORT: length 30.5
  BOTTOM w0.152: J17.16 97.72,85.16 97.72,84.38 97.03,83.69 97.03,82.29 99.29,80.02 D35.2 98.81,79.03 98.81,76.6 100.54,74.86 104.16,74.86 104.78,74.24 106.32,74.24 106.73,73.83 114.35,73.83 114.68,73.5 R176.2 115.18,72.13 Q16.3
HP_BUTTON_DET: length 54.7
  TOP w0.152: v2(50.87,66.92) 50.87,67.22 51.27,67.62 J3.46 ; v1(42.4,84.28) 41.78,84.9 41.78,88.58 41.4,88.97 39.01,88.97 38.73,89.25 38.73,95.76 38.23,96.26 36.45,96.26 36.07,96.65 36.07,98.93 35.69,99.31 v1(34.24,99.31)
  ART04 w0.152: v1(42.4,84.28) 42.88,84.75 42.88,85.51 43.18,85.82 44.75,85.82 45.44,85.13 45.44,82.54 44.32,81.42 44.32,71.16 46,69.48 47.07,69.48 47.37,69.18 47.37,68.52 47.68,68.21 50.16,68.21 50.47,67.91 50.47,67.32 v2(50.87,66.92)
  BOTTOM w0.152: v1(34.24,99.31) 34.24,99.1 34.41,98.93 C121.1 R118.1 R116.2
HP_PLUG_IN_DET: length 156.3
  TOP w0.152: v2(76.84,17.69) J2.46
  ART03 w0.152: v1(42.4,85.28) 40.54,85.28 39.9,85.92 v1(39.9,98.17)
  ART04 w0.152: v2(76.84,17.69) 77.22,17.31 77.22,16.47 77.62,16.07 91.74,16.07 92.05,16.37 92.05,47.94 91.74,48.25 78.56,48.25 77.98,47.67 51.82,47.67 51.29,48.19 51.29,68.03 50.62,68.7 48.09,68.7 47.88,68.91 47.88,69.56 47.57,69.86 46.3,69.86 44.7,71.47 44.7,81.14 45.82,82.26 45.82,85.38 44.96,86.25 42.71,86.25 42.4,85.94 v1(42.4,85.28)
  BOTTOM w0.152: v1(39.9,98.17) 39.57,98.5 39.57,100.61 39.91,100.96 R120.2
I2C0_SCL_M2: length 152.3
  TOP w0.152: v1(85.19,12.84) 84.68,12.33 84.07,12.33 83.72,12.68 83.72,13.5 83.95,13.73 83.95,17.03 84.44,17.53 J2.84 ; v1(84.96,13.86) 86.28,13.86 86.79,13.35 88.75,13.35 89.05,13.65 89.05,17.55 89.94,18.43 92.53,18.43 92.84,18.73 92.84,24.14 93.7,25.01 103.15,25.01 103.5,25.36 103.5,26.68 104.14,27.32 109.73,27.32 111.4,29 114.71,29 115.32,29.61 115.32,35.91 115.87,36.46 118.49,36.46 118.9,36.06 120.16,36.06 120.47,36.36 U35.6 120.47,38.16 120.9,38.6 123.29,38.6 123.6,38.9 123.6,42.36 123.95,42.71 134.69,42.71 134.99,43.01 U44.22 134.99,48.4 135.29,48.71 138.05,48.71 138.35,49.01 138.35,58.31 v1(138.99,58.94) ; J32.6 164.22,78.85 163.86,79.21 157.81,79.21 157.43,78.83 157.43,66.11 v1(158.08,65.46)
  ART03 w0.152: v1(158.08,65.46) 157.56,65.98 152.43,65.98 151.69,65.24 151.69,59.98 151.28,59.58 146.96,59.58 146.25,58.87 139.06,58.87 v1(138.99,58.94)
  BOTTOM w0.152: v1(84.96,13.86) 84.96,13.07 v1(85.19,12.84)
I2C0_SDA_M2: length 148.6
  TOP w0.152: J32.5 164.43,79.35 164,79.78 157.21,79.78 156.87,79.44 156.87,65.67 v1(157.08,65.46) ; J2.86 84.84,17.42 84.45,17.03 84.45,13.68 84.86,13.27 86.18,13.27 86.49,12.97 89.13,12.97 89.43,13.27 89.43,17.39 90.09,18.05 92.69,18.05 93.22,18.58 93.22,23.99 93.88,24.65 103.53,24.65 103.89,25.01 103.89,26.53 104.3,26.94 109.85,26.94 111.53,28.62 114.96,28.62 115.7,29.35 115.7,35.75 116.03,36.08 118.36,36.08 118.77,35.68 120.39,35.68 121.12,36.41 U35.5 121.12,37.89 121.42,38.19 123.9,38.19 124.21,38.5 124.21,41.75 124.51,42.06 135.34,42.06 135.64,42.36 U44.23 135.64,47.95 135.89,48.2 138.52,48.2 138.83,48.5 138.83,57.85 v1(138.98,58)
  ART03 w0.152: v1(138.98,58) 139.44,57.55 145.8,57.55 147.45,59.2 151.87,59.2 152.27,59.6 152.27,64.31 152.86,64.9 156.51,64.9 v1(157.08,65.46)
I2C1_SCL_M2: length 286.2
  TOP w0.152: U5.6 20.19,84.62 v1(20.46,84.34) ; J2.88 85.24,17.25 v2(84.84,16.85)
  ART04 w0.152: v2(84.84,16.85) 84.61,17.09 84.61,30.83 85.57,31.79 85.57,46.57 85.27,46.88 50.22,46.88 49.61,46.27 42.8,46.27 42.45,46.61 42.45,67.91 42.03,68.34 41.73,68.34 39.7,70.37 39.7,73.22 39.09,73.83 33.48,73.83 32.82,74.49 28.4,74.49 28.02,74.87 24.99,74.87 24.66,75.2 23.95,75.2 23.7,75.45 23.7,80.71 23.32,81.09 21.13,81.09 20.83,81.4 20.83,83.98 v1(20.46,84.34)
  BOTTOM w0.152: J33.6 167.81,72.35 168.28,71.87 170.21,71.87 171.37,70.71 171.37,32 169.85,30.48 163.09,30.48 162.78,30.18 162.78,18.45 162.22,17.89 155.43,17.89 155.06,17.52 155.06,11.74 154.76,11.43 91.32,11.43 87.63,15.13 85.73,15.13 84.84,16.01 v2(84.84,16.85)
I2C1_SDA_M2: length 282.8
  TOP w0.152: v1(21.46,84.34) 21.12,84.34 20.69,84.77 U5.7 ; v2(85.64,17.69) J2.90
  ART04 w0.152: v2(85.64,17.69) 85.64,30.51 86.23,31.1 86.23,46.95 85.93,47.26 49.86,47.26 49.3,46.7 43.41,46.7 43,47.11 43,68.39 40.28,71.11 40.28,74.26 39.67,74.87 28.93,74.87 27.89,75.91 24.97,75.91 24.59,76.29 24.59,81.19 24.1,81.68 22.15,81.68 21.84,81.98 21.84,83.96 v1(21.46,84.34)
  BOTTOM w0.152: J33.5 167.56,71.85 167.91,71.5 170.06,71.5 171,70.56 171,32.21 169.75,30.96 162.61,30.96 162.31,30.66 162.31,18.72 161.9,18.31 155.04,18.31 154.53,17.8 154.53,12.11 154.23,11.81 91.54,11.81 87.82,15.53 86.21,15.53 85.22,16.52 85.22,17.27 v2(85.64,17.69)
I2C2_SCL_M4: length 263.1
  TOP w0.152: J2.54 v2(78.44,17.69) 77.47,16.72 R360.2 ; J14.9 v1(8.13,79.07)
  TOP w0.173: J34.6 163.9,61.46 v1(162.77,62.58)
  ART03 w0.152: v1(34,31.12) 35.11,30.01 57.38,30.01 59.31,28.08 64.57,28.08 64.87,28.39 78.36,28.39 v2(78.44,28.31) 78.9,28.77 88.32,28.77 89.53,29.99 99.48,29.99 102.87,26.6 117.69,26.6 118.43,25.86 141.28,25.86 146,30.57 146,37.43 146.18,37.61 146.18,56.79 147.62,58.23 153.01,58.23 153.47,58.69 153.47,62.15 153.9,62.58 v1(162.77,62.58)
  ART04 w0.152: v2(78.44,17.69) v2(78.44,28.31)
  BOTTOM w0.152: v1(8.13,79.07) 8.56,79.51 8.56,80.99 8.86,81.29 12.37,81.29 12.85,80.81 30.18,80.81 30.46,80.53 30.46,73.89 28.55,71.97 28.55,63.24 28.85,62.93 31.88,62.93 32.18,62.63 32.18,57.65 33.1,56.74 33.1,42.48 34.65,40.93 34.65,31.76 v1(34,31.12)
I2C2_SDA_M4: length 263.4
  TOP w0.152: J14.10 8.63,78.57 v1(9.13,79.07) ; R361.2 78.49,16.81 v2(78.44,16.85) 78.84,17.25 J2.56
  TOP w0.173: v1(163.77,62.58) 164.4,61.96 J34.5
  ART03 w0.152: v1(34,32.12) 35.07,31.05 57.51,31.05 59.97,28.59 64.11,28.59 64.74,29.22 76.89,29.22 77.37,29.71 v2(78.86,29.71) 79.42,29.15 88.06,29.15 89.34,30.43 99.73,30.43 103.15,27.02 117.83,27.02 118.63,26.22 140.38,26.22 144.73,30.57 144.73,35.45 145.22,35.94 145.22,37.59 145.82,38.19 145.82,57.04 147.5,58.71 152.4,58.71 152.88,59.2 152.88,62.65 153.26,63.03 163.32,63.03 v1(163.77,62.58)
  ART04 w0.152: v2(78.86,29.71) 78.86,17.27 v2(78.44,16.85)
  BOTTOM w0.152: v1(34,32.12) 34,40.53 32.54,42 32.54,56.5 31.67,57.37 31.67,61.43 31.37,61.74 28.37,61.74 28.07,62.04 28.07,72.21 29.67,73.81 29.67,79.82 29.21,80.28 27.56,80.28 27.13,79.85 25.32,79.85 24.74,80.43 18.19,80.43 17.3,79.54 13.44,79.54 12.17,80.81 9.96,80.81 9.6,80.46 9.6,79.9 9.13,79.42 v1(9.13,79.07)
